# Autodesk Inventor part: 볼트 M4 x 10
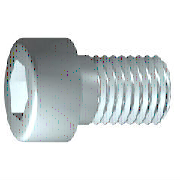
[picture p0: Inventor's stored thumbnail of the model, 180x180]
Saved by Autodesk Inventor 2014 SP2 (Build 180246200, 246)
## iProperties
Created: 2012-02
Part Number: 볼트 M4 x 10
Material: 스테인리스강
Description: 6각 소켓 머리 캡 나사
Document SubType Name: Modeling
Standard: ISO 4762
Designer: mduedu
Standard Revision: Fourth edition 2004-03-01
Standards Organization: ISO
Language: ko-KR
Size Designation: M4 x 10
Categories: <MemberInstance><Categories><Category DisplayName="조임쇠" InternalName="e4da775c-781d-43d5-af7c-5136215cf5a6" Mnemonic="FSTN"><Category DisplayName="볼트" InternalN
Density: 8.08 g/cm^3
Appearance: 반광택
IsCustomPart: 0
Author: mduedu
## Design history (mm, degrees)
sketch "스케치1"
  geometry: L1 (-1, 0)-(10, 0); L2 (10, 0)-(10, 2); L3 (10, 2)-(1.75, 2); L4 (1.75, 2)-(1.32, 2); L5 (1.32, 2)-(0, 2); L6 (0, 2)-(0, 3.5); L7 (0, 3.5)-(-4, 3.5); L8 (-4, 3.5)-(-4, 1.732); L9 (-4, 1.732)-(-2, 1.732); L10 (-2, 1.732)-(-1, 0); L11 (-6.8, 0)-(12.8, 0) reference; L12 (0, -0.7)-(0, 4.2) reference; L13 (1.75, 2)-(0, 2)
  constraints: 22 end point, 6 parallel, 2 collinear, 2 perpendicular, 1 horizontal, 1 point on line
  dimensions: "d1" = 8.25 distance from line of L3.end L2 (= GEL); "d2" = 0.42952 distance of L4.end L3.end (computed from GAL); "d3" = 4 distance between parallel lines of L8 L6 (= KOH); "d4" = 2 distance of L8.end L9.end (= INTI); "d5" = 60 deg angle of L10 L1; "d6" = 4 diameter of L3 L1 (= GD); "d7" = 4 diameter of L5 L1 (= BDM); "d8" = 3.4641 diameter of L9 L1 (= 1.1547 x SW); "d9" = 7 diameter of L7 L1 (= KOD); "d26" = 10 distance between parallel lines of L12 L2 (= NLG)
revolve "본체" sketch "스케치1" stored, may be unused: angle "d10" = 90 deg
sketch "스케치2"
  geometry: L1 (0, -4.9)-(0, 4.9) reference; L2 (-4.9, 0)-(4.9, 0) reference; L3 (1.732, 0)-(0.866, -1.5); L4 (0.866, -1.5)-(-0.866, -1.5); L5 (-0.866, -1.5)-(-1.732, 0); L6 (-1.732, 0)-(-0.866, 1.5); L7 (-0.866, 1.5)-(0.866, 1.5); L8 (0.866, 1.5)-(1.732, 0); 2 further points
  constraints: 12 end point, 1 coincident, 1 horizontal alignment, 1 point on line, 12 other
extrude "슬롯" join sketch "스케치2" stored distance "d11" = 10; taper "d12" = 0 deg
workplane "Work Plane1"
fillet "Fillet2" dims "d30" = 0.1 (= R)
body "Solid1"
fillet "모깎기1" dims "d17" = 0.4 (= RR)
feature "스레드" dims "d13" = 8.25 (= GEL), "d14" = 0
chamfer "모따기1" distance "d15" = 0.42941 (= -0.5 x SPD + 0.5 x GD); stored, may be unused: second distance "d16" = 0.42941 (= GUL), angle "d27" = 45 deg
other parameters: "GD" = 4 [user parameter; used in 2 equation terms], "NLG" = 10 [user parameter; used in 1 equation term], "GEL" = 8.25 [user parameter; used in 2 equation terms], "KOD" = 7 [user parameter; used in 1 equation term], "KOH" = 4 [user parameter; used in 1 equation term], "INTI" = 2 [user parameter; used in 1 equation term], "GAL" = 0.42941 (= 0.61345 x PTC) [user parameter; used in 1 equation term], "GUL" = 0.42941 (= 0.61345 x PTC) [user parameter; used in 1 equation term], "BDM" = 4 (= NND) [user parameter; used in 1 equation term], "SW" = 3 [user parameter; used in 2 equation terms], "RR" = 0.4 [user parameter; used in 1 equation term], "SPD" = 3.14117 (= NND - 1.2269 x PTC) [user parameter; used in 1 equation term], "d19" = 0, "d28" = 0, "d29" = 0, "R" = 0.1 [user parameter; used in 1 equation term], "TOA" = 30 deg [user parameter], "GD1" = 3.14117 (= THREADDIA - 1.2269 x PTC) [user parameter], "THREADDIA" = 4 [user parameter; used in 1 equation term], "FAWI" = 45 deg [user parameter], "TPU" = 14.28571 (computed from PTC) [user parameter], "PTC" = 0.7 [user parameter; used in 5 equation terms], "NND" = 4 [user parameter; used in 2 equation terms], "E0" = 3.465 (= 1.155 x SW) [user parameter]
